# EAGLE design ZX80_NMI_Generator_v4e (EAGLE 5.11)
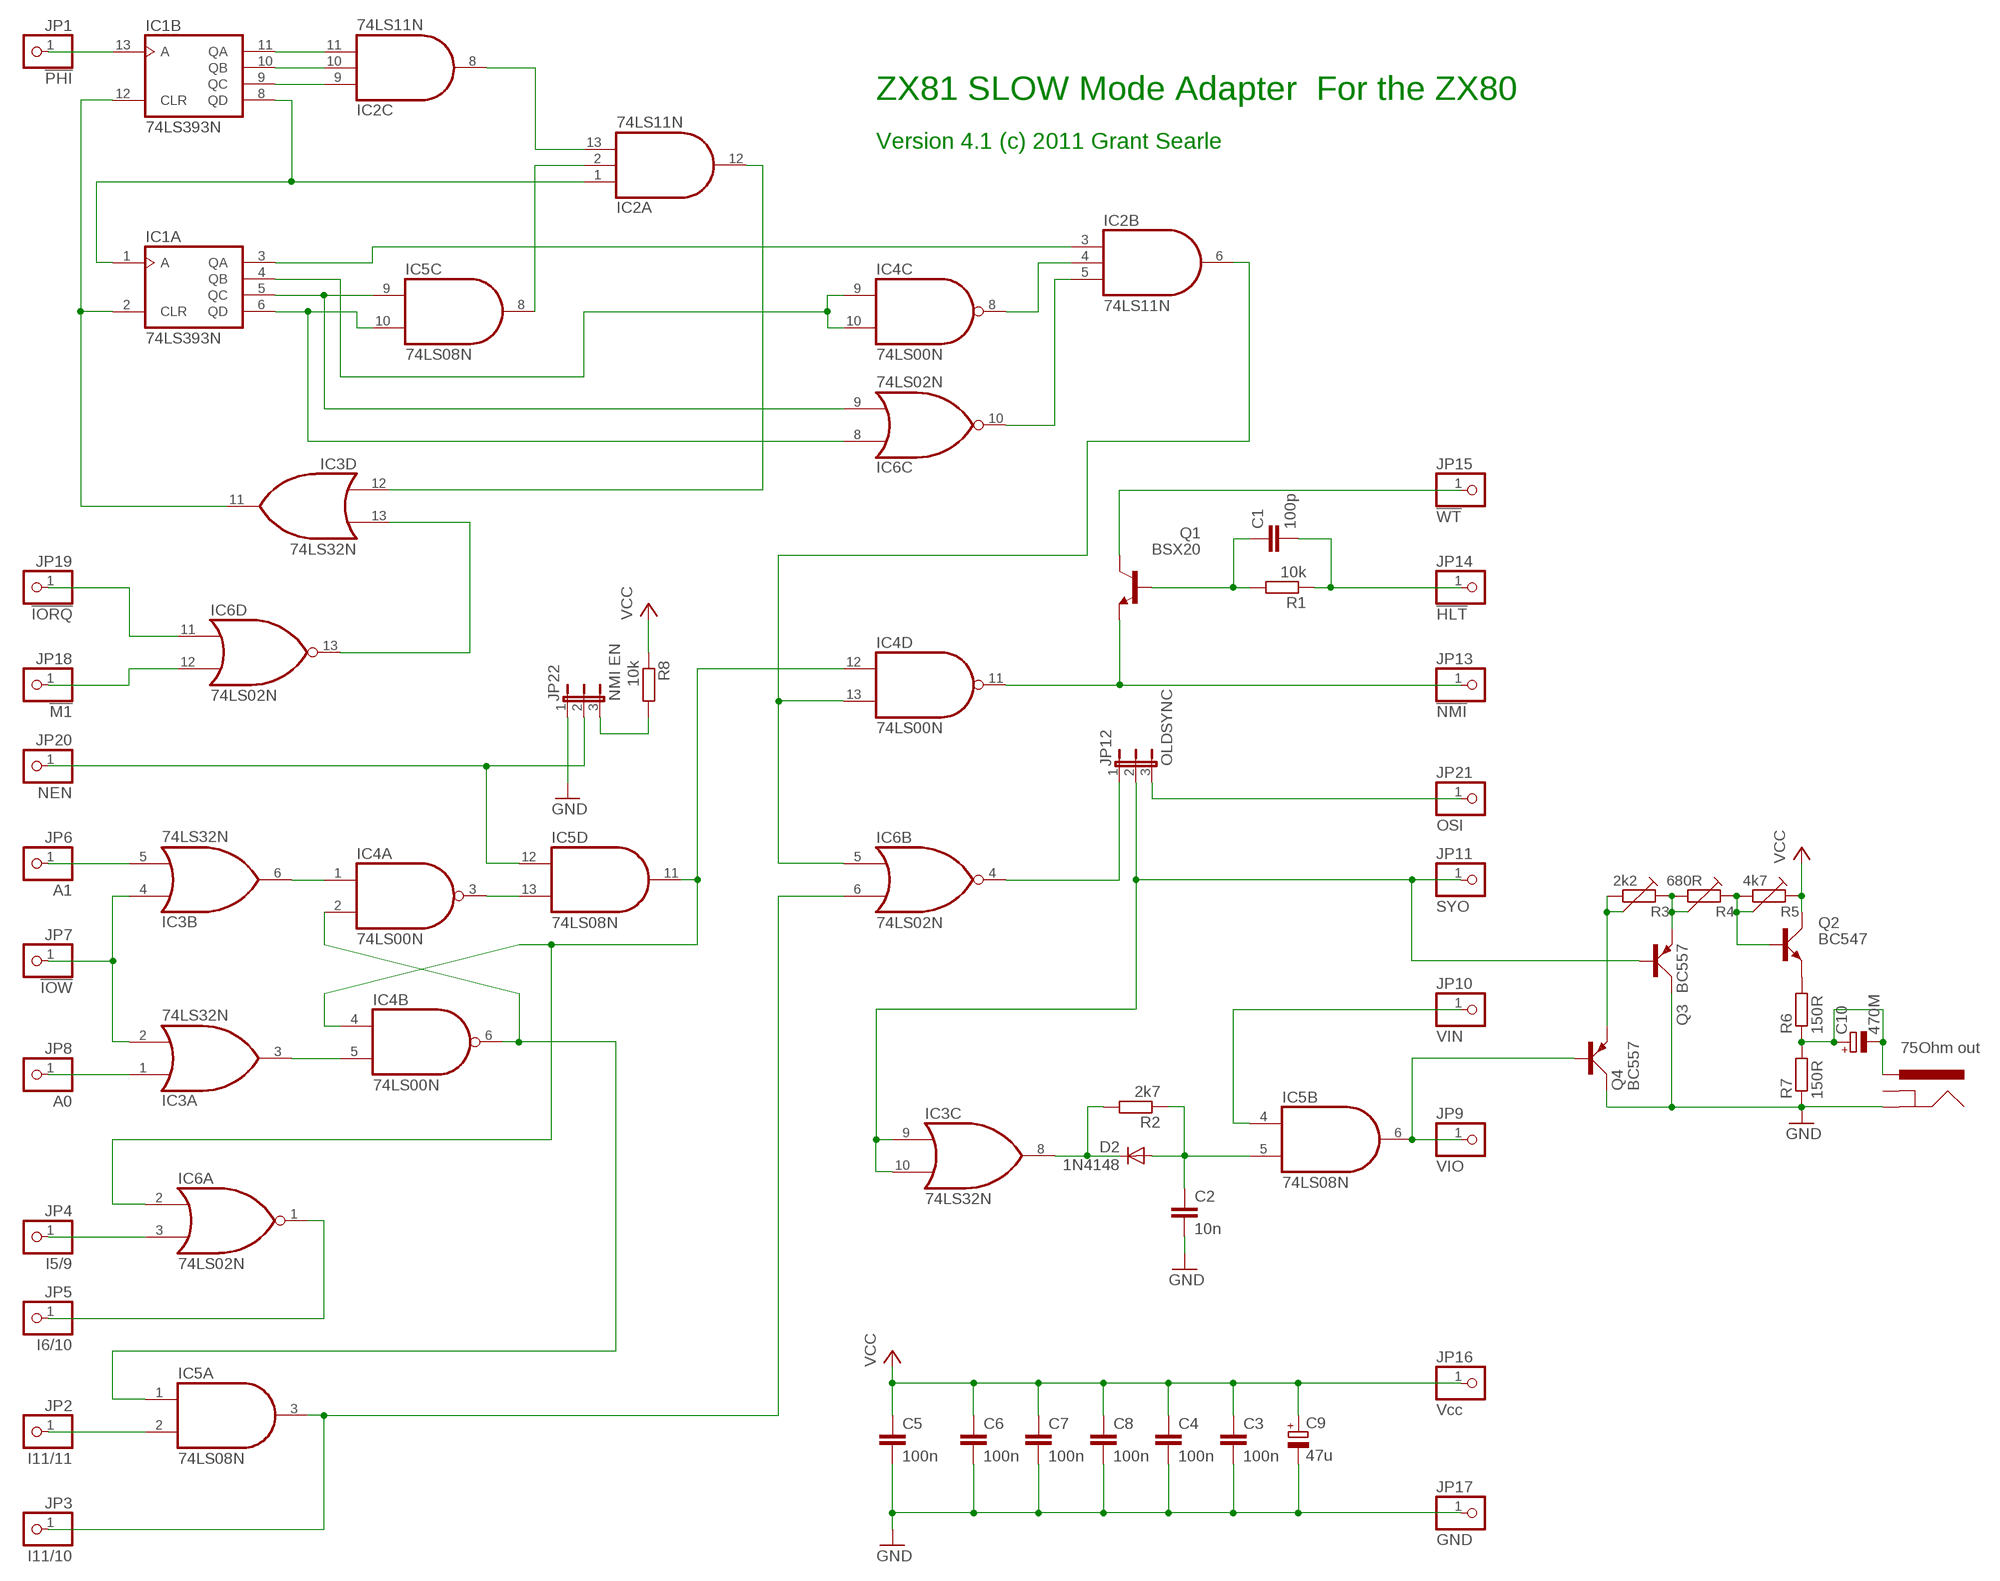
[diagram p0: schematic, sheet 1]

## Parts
C1  100p  C-EU025-025X050  [C025-025X050]
C2  10n  C-EU025-025X050  [C025-025X050]
C3  100n  C-EU025-025X050  [C025-025X050]
C4  100n  C-EU025-025X050  [C025-025X050]
C5  100n  C-EU025-025X050  [C025-025X050]
C6  100n  C-EU025-025X050  [C025-025X050]
C7  100n  C-EU025-025X050  [C025-025X050]
C8  100n  C-EU025-025X050  [C025-025X050]
C9  47u  CPOL-EUE2.5-7  [E2,5-7]
C10  470M  CPOL-EUE2.5-7  [E2,5-7]
D2  1N4148  1N4148DO35-10  [DO35-10]
IC1  74LS393N  [DIL14]
IC2  74LS11N  [DIL14]
IC3  74LS32N  [DIL14]
IC4  74LS00N  [DIL14]
IC5  74LS08N  [DIL14]
IC6  74LS02N  [DIL14]
J1  POWER_JACKRCA  [RCA]
JP1  !PHI  PINHD-1X1  [1X01]
JP2  I11/11  PINHD-1X1  [1X01]
JP3  I11/10  PINHD-1X1  [1X01]
JP4  I5/9  PINHD-1X1  [1X01]
JP5  I6/10  PINHD-1X1  [1X01]
JP6  A1  PINHD-1X1  [1X01]
JP7  !IOW  PINHD-1X1  [1X01]
JP8  A0  PINHD-1X1  [1X01]
JP9  VIO  PINHD-1X1  [1X01]
JP10  VIN  PINHD-1X1  [1X01]
JP11  SYO  PINHD-1X1  [1X01]
JP12  OLDSYNC  JP2E  [JP2]
JP13  !NMI  PINHD-1X1  [1X01]
JP14  !HLT  PINHD-1X1  [1X01]
JP15  !WT  PINHD-1X1  [1X01]
JP16  Vcc  PINHD-1X1  [1X01]
JP17  GND  PINHD-1X1  [1X01]
JP18  !M1  PINHD-1X1  [1X01]
JP19  !IORQ  PINHD-1X1  [1X01]
JP20  NEN  PINHD-1X1  [1X01]
JP21  OSI  PINHD-1X1  [1X01]
JP22  NMI EN  JP2E  [JP2]
Q1  BSX20  [TO18]
Q2  BC547  [SOT54A]
Q3  BC557  [SOT54A]
Q4  BC557  [SOT54A]
R1  10k  R-EU_0207/10  [0207/10]
R2  2k7  R-EU_0207/10  [0207/10]
R3  2k2  TRIMRPT6H  [PT6H]
R4  680R  TRIMRPT6H  [PT6H]
R5  4k7  TRIMRPT6H  [PT6H]
R6  150R  R-EU_0207/10  [0207/10]
R7  150R  R-EU_0207/10  [0207/10]
R8  10k  R-EU_0207/10  [0207/10]

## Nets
GND [power]: C2.2 C3.2 C4.2 C5.2 C6.2 C7.2 C8.2 C9.- J1.BARREL(GND) JP17.1 JP22.1 Q3.C Q4.C R7.1
N$1: IC3.1(A:I0) JP8.1
N$2: IC3.5(B:I1) JP6.1
N$3: IC1.13(B:A) JP1.1
N$4: IC1.2(A:CLR) IC1.12(B:CLR) IC3.11(D:O)
N$5: IC1.1(A:A) IC1.8(B:QD) IC2.1(A:I0)
N$6: IC2.8(C:O) IC2.13(A:I2)
N$7: IC4.2(A:I1) IC4.6(B:O) IC5.1(A:I0)
N$8: IC1.11(B:QA) IC2.11(C:I2)
N$9: IC1.10(B:QB) IC2.10(C:I1)
N$10: IC1.9(B:QC) IC2.9(C:I0)
N$11: IC1.5(A:QC) IC5.9(C:I0) IC6.9(C:I1)
N$12: IC5.2(A:I1) JP2.1
N$13: IC3.13(D:I1) IC6.13(D:O)
N$14: IC1.3(A:QA) IC2.3(B:I0)
N$15: IC5.3(A:O) IC6.6(B:I1) JP3.1
N$16: IC4.4(B:I0) IC4.12(D:I0) IC5.11(D:O) IC6.2(A:I0)
N$17: IC5.6(B:O) JP9.1 Q4.B
N$18: IC4.3(A:O) IC5.13(D:I1)
N$19: IC4.11(D:O) JP13.1 Q1.1(E)
N$20: JP15.1 Q1.3(C)
N$21: IC2.2(A:I1) IC5.8(C:O)
N$22: IC2.4(B:I1) IC4.8(C:O)
N$23: IC2.5(B:I2) IC6.10(C:O)
N$24: IC2.6(B:O) IC4.13(D:I1) IC6.5(B:I0)
N$25: IC3.2(A:I1) IC3.4(B:I0) JP7.1
N$26: IC3.3(A:O) IC4.5(B:I1)
N$27: IC3.6(B:O) IC4.1(A:I0)
N$28: IC2.12(A:O) IC3.12(D:I0)
N$29: IC5.4(B:I0) JP10.1
N$30: D2.C IC3.8(C:O) R2.2
N$31: IC1.6(A:QD) IC5.10(C:I1) IC6.8(C:I0)
N$32: IC6.12(D:I1) JP18.1
N$33: IC6.3(A:I1) JP4.1
N$34: C1.1 Q1.2(B) R1.2
N$35: C1.2 JP14.1 R1.1
N$36: IC6.11(D:I0) JP19.1
N$37: IC1.4(A:QB) IC4.9(C:I0) IC4.10(C:I1)
N$38: C2.1 D2.A IC5.5(B:I1) R2.1
N$39: IC6.4(B:O) JP12.1
N$40: IC5.12(D:I0) JP20.1 JP22.2
N$41: IC3.9(C:I0) IC3.10(C:I1) JP11.1 JP12.2 Q3.B
N$42: JP12.3 JP21.1
N$43: IC6.1(A:O) JP5.1
N$44: Q2.E R6.2
N$45: Q4.E R3.2 R3.3
N$46: Q3.E R3.1 R4.2 R4.3
N$47: Q2.B R4.1 R5.2 R5.3
N$49: C10.+ C10.- J1.BREAK(PWR) R6.1 R7.2
N$50: JP22.3 R8.2
VCC [power]: C3.1 C4.1 C5.1 C6.1 C7.1 C8.1 C9.+ JP16.1 Q2.C R5.1 R8.1
Unconnected: J1.SPRING(GNDBREAK)

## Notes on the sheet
- ZX81 SLOW Mode Adapter  For the ZX80
- Version 4.1 (c) 2011 Grant Searle
- 75Ohm out

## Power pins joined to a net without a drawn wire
GND: IC1.7(P:GND) IC2.7(P:GND) IC3.7(P:GND) IC4.7(P:GND) IC5.7(P:GND) IC6.7(P:GND)
VCC: IC1.14(P:VCC) IC2.14(P:VCC) IC3.14(P:VCC) IC4.14(P:VCC) IC5.14(P:VCC) IC6.14(P:VCC)

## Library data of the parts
C1-C8 = resistor:C-EU: CAPACITOR, European symbol
C9 C10 = rcl:CPOL-EU: POLARIZED CAPACITOR, European symbol
D2 = diode:1N4148: DIODE
IC1 = 74xx-us:74*393: Dual 4-bit decade and binary COUNTER
IC2 = 74xx-us:74*11: Triple 3-input AND gate
IC3 = 74xx-us:74*32: Quad 2-input OR gate
IC4 = 74xx-us:74*00: Quad 2-input NAND gate
IC5 = 74xx-us:74*08: Quad 2-input AND gate
IC6 = 74xx-us:74*02: Quad 2-input NOR gate
J1 = SparkFun:POWER_JACK: Power Jack This is the standard 5.5mm barrel jack for power. The PTH is the most common, proven, reliable, footprint. All others are experimental. The Slot footprint only works if the mill layer is transmitted to the PCB fab house so be warned. Spark Fun Electronics SKU : PRT-00119. Mating wall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
JP1-JP11 JP13-JP21 = pinhead:PINHD-1X1: PIN HEADER
JP12 JP22 = jumper:JP2E: JUMPER
Q1 = transistor-npn:BSX20*: NPN Transistor
Q2 = transistor-small-signal:BC547: NPN TRANSISTOR
Q3 Q4 = transistor-small-signal:BC557: PNP TRANSISTOR
R1 R2 R6-R8 = resistor:R-EU_: RESISTOR, European symbol
R3-R5 = #PaJa_30:TRIMR: Trimr

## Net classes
0 default: width 0.254 mm, clearance 0.254 mm
1 power: width 0.61 mm, clearance 0.254 mm

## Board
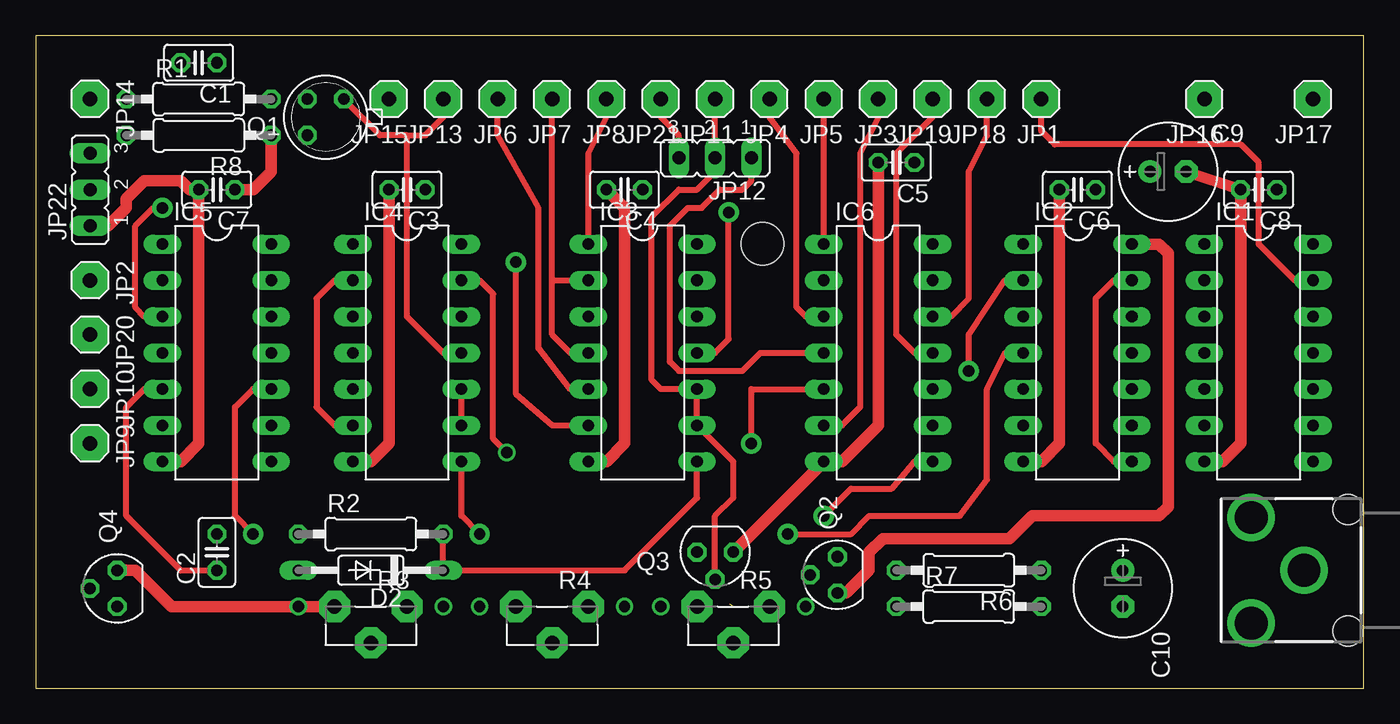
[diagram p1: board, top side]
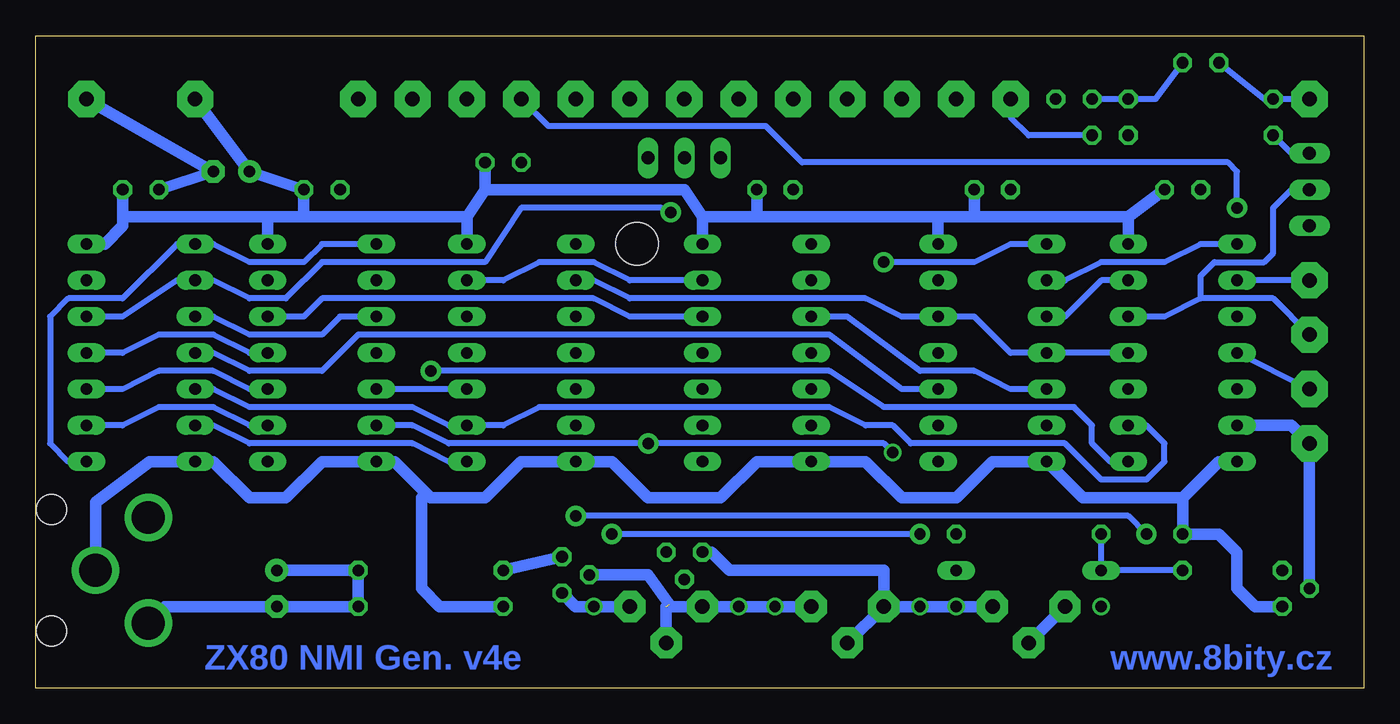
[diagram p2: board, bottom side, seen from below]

Size 93.09 x 45.72 mm. Coordinates in mm from the lower left corner, seen from the top.
Outline: 0,0 93.09,0 93.09,45.72 0,45.72 0,0
Copper layers (1*16): Top 0.035mm / dielectric 1.5mm / Bottom 0.035mm
Design rules "trida4_12.5mil": minimum track width 12.5mil, minimum drill 0.8mm, track to track 12.5mil, track to pad 12.5mil, pad to pad 12.5mil, via to via 12.5mil, smd to smd 8mil, copper to edge 0.1mm, drill to drill 1.25mm, minimum pad ring 10mil, minimum via ring 8mil, stop-mask expansion 4mil, vias tented up to drill 0mil, thermal gap 10mil
Holes 3 mm at 50.95,31.13

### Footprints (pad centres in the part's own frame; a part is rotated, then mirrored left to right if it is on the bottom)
C025-025X050 = drill 0.813 octagon: 1 -1.27,0; 2 1.27,0
E2,5-7 = drill 0.813 pad 1.6 round: + -1.27,0 | drill 0.813 pad 1.6 octagon: - 1.27,0
DO35-10 = drill 0.813 long: A 5.08,0; C -5.08,0
DIL14 = drill 0.813 long: 1 -7.62,-3.81; 2 -5.08,-3.81; 3 -2.54,-3.81; 4 0,-3.81; 5 2.54,-3.81; 6 5.08,-3.81; 7 7.62,-3.81; 8 7.62,3.81; 9 5.08,3.81; 10 2.54,3.81; 11 0,3.81; 12 -2.54,3.81; 13 -5.08,3.81; 14 -7.62,3.81
RCA = drill 2.3 round: BARREL 0,0; BREAK 3.7,3.7; SPRING 3.7,-3.7 | hole 2.1: -3.1,4.25; -3.1,-4.25
1X01 = drill 1.016 pad 2.54 octagon: 1 0,0
JP2 = drill 0.914 long: 1 -2.54,0; 2 0,0; 3 2.54,0
TO18 = drill 0.813 octagon: 1 -1.27,-1.27; 2 1.27,-1.27; 3 1.27,1.27
SOT54A = drill 0.813 octagon: B 0,1.905; C -1.27,0; E 1.27,0
0207/10 = drill 0.813 octagon: 1 -5.08,0; 2 5.08,0
PT6H = drill 1.016 pad 2.184 octagon: 1 -2.54,-1.27; 2 2.54,-1.27; 3 0,1.27

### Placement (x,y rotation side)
C1  11.43,43.81 180 top
C2  12.7,9.53 90 top
C3  26.04,34.92 180 top
C4  41.27,34.92 180 top
C5  60.33,36.83 180 top
C6  73.03,34.92 180 top
C7  12.7,34.92 180 top
C8  85.72,34.92 180 top
C9  79.38,36.2 0 top
C10  76.2,6.99 270 top
D2  23.5,8.26 180 top
IC1  85.72,23.5 270 top
IC2  73.03,23.5 270 top
IC3  42.55,23.5 270 top
IC4  26.04,23.5 270 top
IC5  12.7,23.5 270 top
IC6  59.05,23.5 270 top
J1  88.9,8.26 180 top
JP1  70.48,41.27 180 top
JP2  3.81,28.57 270 top
JP3  59.05,41.27 180 top
JP4  51.44,41.27 180 top
JP5  55.24,41.27 180 top
JP6  32.38,41.27 180 top
JP7  36.2,41.27 180 top
JP8  40.01,41.27 180 top
JP9  3.81,17.14 270 top
JP10  3.81,20.95 270 top
JP11  47.62,41.27 180 top
JP12  47.62,37.15 180 top
JP13  28.57,41.27 180 top
JP14  3.81,41.27 270 top
JP15  24.77,41.27 180 top
JP16  81.92,41.27 180 top
JP17  89.53,41.27 180 top
JP18  66.67,41.27 180 top
JP19  62.87,41.27 180 top
JP20  3.81,24.77 270 top
JP21  43.81,41.27 180 top
JP22  3.81,34.92 90 top
Q1  20.32,40.01 180 top
Q2  56.2,7.94 90 top
Q3  47.62,9.53 180 top
Q4  5.71,6.99 90 top
R1  11.43,41.27 0 top
R2  23.5,10.79 0 top
R3  23.5,4.45 180 top
R4  36.2,4.45 180 top
R5  48.9,4.45 180 top
R6  65.41,8.26 180 top
R7  65.41,5.71 0 top
R8  11.43,38.73 180 top

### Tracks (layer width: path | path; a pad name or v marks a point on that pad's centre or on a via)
GND
  Top 0.813: IC1.7 83.19,15.88 84.45,17.14 C8.2 C9.- | C6.2 71.75,17.14 70.48,15.88 IC2.7 | C5.2 59.05,18.41 56.52,15.88 IC6.7 Q3.C | C4.2 41.27,33.66 41.27,17.14 40.01,15.88 IC3.7 | C3.2 24.77,17.14 23.5,15.88 IC4.7 | IC5.7 10.16,15.88 11.43,17.14 C7.2 10.79,34.92 10.16,35.56 7.62,35.56 6.35,34.29 6.35,33.66 5.08,32.38 JP22.1
  Bottom 0.61: IC1.7 82.55,15.88
  Bottom 0.813: IC5.7 10.16,15.88 12.7,13.34 | 12.7,13.34 19.68,13.34 IC4.7 26.04,15.88 28.57,13.34 32.38,13.34 34.92,15.88 IC3.7 42.55,15.88 45.09,13.34 50.16,13.34 52.7,15.88 IC6.7 59.05,15.88 61.59,13.34 65.41,13.34 65.72,13.65 | JP17.1 C9.- C8.2 | 65.72,13.65 67.94,15.88 IC2.7 73.03,15.88 75.56,13.34 78.11,13.34 80.64,15.88 IC1.7 | 12.7,13.34 C2.2 10.16,10.79 8.89,9.53 8.89,6.99 7.62,5.71 Q4.C | J1.BARREL 88.9,13.02 85.09,15.88 82.55,15.88 | R7.1 64.77,5.71 66.04,6.99 66.04,13.34 65.72,13.65
N$1
  Top 0.406: JP8.1 40.01,40.01 38.73,37.47 IC3.1
N$2
  Top 0.406: IC3.5 37.47,20.95 35.24,23.81 35.24,33.66 32.38,38.73 JP6.1
N$3
  Top 0.406: IC1.13 88.27,28.57 85.72,31.11 85.72,36.83 84.45,38.1 71.44,38.1 70.48,39.05 JP1.1
N$4  (via drill 0.8 pad 1.42)
  Top 0.406: v48.58,33.34 48.58,24.45 47.62,23.5 IC3.11
  Bottom 0.406: IC1.12 87,26.04 83.19,28.57 IC1.2 80.64,28.57 78.11,27.3 75.56,27.3 73.03,29.84 61.59,29.84 59.05,33.66 49.21,33.66 v48.58,33.34
N$5
  Bottom 0.406: IC1.8 90.81,15.88 92.08,17.14 92.08,26.04 90.81,27.3 87,27.3 83.19,31.11 IC1.1 80.64,31.11 78.11,29.84 74.3,29.84 73.03,31.11 IC2.1
N$6
  Top 0.406: IC2.13 75.56,28.57 74.3,27.3 74.3,17.14 75.56,15.88 IC2.8
N$7
  Top 0.406: IC4.6 20.95,18.41 19.68,19.68 19.68,27.3 20.95,28.57 IC4.2
  Bottom 0.406: IC5.1 11.43,31.11 13.97,29.84 18.41,29.84 20.95,28.57 IC4.2
N$8
  Bottom 0.406: IC1.11 87,23.5 84.45,24.77 80.64,24.77 78.11,23.5 IC2.11
N$9
  Bottom 0.406: IC1.10 87,20.95 84.45,22.23 80.64,22.23 78.11,20.95 IC2.10
N$10
  Bottom 0.406: IC1.9 87,18.41 84.45,19.68 80.64,19.68 78.11,18.41 IC2.9
N$11
  Bottom 0.406: IC5.9 15.24,18.41 13.97,17.14 13.97,15.88 15.24,14.61 18.41,14.61 20.95,17.14 31.75,17.14 33.02,18.41 34.92,18.41 37.47,19.68 57.78,19.68 60.33,18.41 IC6.9 64.14,18.41 66.67,19.68 78.11,19.68 80.64,20.95 IC1.5
N$12
  Bottom 0.406: JP2.1 IC5.2
N$13
  Bottom 0.406: IC3.13 51.44,28.57 53.98,29.84 57.78,29.84 60.33,28.57 IC6.13
N$14
  Bottom 0.406: IC1.3 80.64,26.04 78.11,24.77 73.03,24.77 71.75,26.04 IC2.3
N$15  (via drill 0.8 pad 1.42)
  Top 0.406: IC6.6 56.52,18.41 57.78,19.68 57.78,37.47 59.05,40.01 JP3.1 | IC5.3 7.62,26.04 6.99,26.67 6.99,32.38 8.26,33.66 v8.89,33.66
  Bottom 0.406: v8.89,33.66 8.89,36.2 9.53,36.83 39.37,36.83 41.91,39.37 57.15,39.37 JP3.1
N$16
  Bottom 0.406: IC5.11 IC4.4 24.77,23.5 27.3,26.04 IC4.12 32.38,26.04 34.92,27.3 51.44,27.3 53.98,28.57 IC6.2
N$17
  Bottom 0.813: IC5.6 5.08,18.41 JP9.1 Q4.B
N$18
  Bottom 0.406: IC4.3 20.95,26.04 18.41,28.57 IC5.13
N$19
  Top 0.406: IC4.11 28.57,23.5 26.04,26.04 26.04,38.73 | Q1.1 24.13,38.73 26.04,38.73 | 26.04,38.73 27.3,38.73 28.57,40.01 JP13.1
N$20
  Bottom 0.406: Q1.3 23.5,38.73 24.77,40.01 JP15.1
N$21  (via drill 0.8 pad 1.42)
  Top 0.406: IC2.2 67.94,28.57 65.41,24.77 v65.41,22.23
  Bottom 0.406: IC5.8 17.78,15.88 19.05,17.14 19.05,18.41 20.32,19.68 33.66,19.68 37.47,22.23 v65.41,22.23
N$22  (via drill 0.8 pad 1.42)
  Top 0.406: IC4.8 29.84,12.06 v31.11,10.79 | v52.7,10.79 57.15,10.79 58.42,12.06 64.77,12.06 66.67,14.61 66.67,20.95 67.94,23.5 IC2.4
  Bottom 0.406: v31.11,10.79 v52.7,10.79
N$23
  Bottom 0.406: IC6.10 IC2.5
N$24  (via drill 0.8, 0.8 pad 1.42)
  Top 0.406: v50.16,17.14 50.16,20.95 IC6.5 | IC4.13 31.11,28.57 32.07,27.62 32.07,17.46 v33.02,16.51
  Bottom 0.406: IC2.6 66.67,18.41 64.14,17.14 v50.16,17.14 33.66,17.14 v33.02,16.51
N$25
  Top 0.406: IC3.4 37.47,23.5 36.2,24.77 36.2,28.57 | 36.2,28.57 IC3.2 | 36.2,28.57 JP7.1
N$26
  Bottom 0.406: IC3.3 36.2,26.04 31.11,22.23 27.3,22.23 24.77,20.95 IC4.5
N$27  (via drill 0.8 pad 1.42)
  Top 0.406: IC3.6 36.2,18.41 33.66,20.64 v33.66,29.84
  Bottom 0.406: IC4.1 24.77,31.11 27.3,29.84 v33.66,29.84
N$28
  Bottom 0.406: IC2.12 74.3,26.04 73.03,27.3 53.98,27.3 51.44,26.04 IC3.12
N$29
  Bottom 0.406: JP10.1 IC5.4
N$30
  Top 0.406: IC3.8 46.35,13.34 41.27,8.26 D2.C R2.2
N$31  (via drill 0.8 pad 1.42)
  Top 0.406: IC5.10 15.24,20.95 13.97,19.68 13.97,12.06 v15.24,10.79 | IC6.8 61.59,15.88 60.01,13.97 57.15,13.97 v55.24,12.06
  Bottom 0.406: v15.24,10.79 16.51,12.06 v55.24,12.06 | IC1.6 80.64,18.41 78.11,17.14 66.67,17.14 64.14,15.88 IC6.8
N$32
  Top 0.406: IC6.12 64.14,26.04 65.41,27.3 65.41,36.2 66.67,38.73 JP18.1
N$33
  Top 0.406: IC6.3 53.98,26.04 53.34,26.67 53.34,37.47 51.44,40.01 JP4.1
N$34
  Bottom 0.406: Q1.2 R1.2 14.61,41.27 C1.1
N$35
  Bottom 0.406: C1.2 6.99,41.27 R1.1 JP14.1
N$36
  Top 0.406: IC6.11 61.59,23.5 60.33,24.77 60.33,37.47 62.87,40.01 JP19.1
N$37
  Top 0.406: IC4.9 IC4.10
  Bottom 0.406: IC4.10 32.38,20.95 37.47,24.77 70.48,24.77 73.03,22.23 78.11,22.23 80.64,23.5 IC1.4
N$38
  Top 0.406: IC5.5 7.62,20.95 6.35,19.68 6.35,12.06 10.16,8.26 C2.1
  Bottom 0.406: C2.1 D2.A R2.1
N$39
  Top 0.406: IC6.4 50.8,23.5 49.53,22.23 45.09,22.23 44.45,22.86 44.45,32.38 45.72,33.66 46.67,33.66 47.94,34.92 49.53,34.92 50.16,35.56 JP12.1
N$40
  Bottom 0.406: IC5.12 13.97,26.04 11.43,27.3 | JP20.1 6.35,27.3 11.43,27.3 | JP22.2 5.08,34.92 6.35,33.66 6.35,30.48 6.99,29.84 10.48,29.84 11.43,28.89 11.43,27.3
N$41
  Top 0.406: JP11.1 JP12.2 47.62,36.2 46.35,34.92 45.09,34.92 43.18,33.02 43.18,21.59 43.81,20.95 IC3.10 IC3.9 48.9,15.88 48.9,13.34 47.62,12.06 Q3.B
N$42
  Top 0.406: JP12.3 45.09,38.73 43.81,40.01 JP21.1
N$43
  Top 0.406: IC6.1 JP5.1
N$44
  Bottom 0.813: Q2.E R6.2
N$45  (via drill 0.8)
  Top 0.813: Q4.E 6.99,8.26 9.53,5.71 v18.41,5.71 R3.2
  Bottom 0.813: R3.3 R3.2
N$46  (via drill 0.8)
  Bottom 0.813: R3.1 v28.57,5.71 v31.11,5.71 R4.2 | R4.2 33.66,8.26 44.45,8.26 45.72,9.53 Q3.E | R4.3 R4.2
N$47  (via drill 0.8)  (1 unrouted)
  Bottom 0.813: R4.1 v41.27,5.71 v43.81,5.71 R5.2 48.58,5.71 50.16,7.94 Q2.B | R5.3 48.9,5.71
N$49
  Bottom 0.813: C10.+ R6.1 R7.2 C10.- 84.04,5.71 J1.BREAK
N$50
  Bottom 0.406: JP22.3 5.08,37.47 R8.2
VCC  (via drill 0.8)
  Top 0.813: Q2.C 56.83,6.67 58.42,8.26 58.42,9.53 59.37,10.48 68.26,10.48 69.85,12.06 78.74,12.06 79.38,12.7 79.38,30.48 78.74,31.11 IC2.14 | C7.1 15.24,34.92 16.51,36.2 R8.1
  Bottom 0.813: 27.3,33.02 29.84,33.02 | 29.84,33.02 42.55,33.02 | 42.55,33.02 46.35,33.02 | 46.35,33.02 47.62,34.92 61.59,34.92 | 61.59,34.92 62.87,33.02 | 62.87,33.02 74.3,33.02 | 74.3,33.02 76.83,33.02 | 76.83,33.02 87,33.02 | 87,33.02 87,32.38 88.27,31.11 IC1.14 | 87,33.02 C8.1 | 76.83,33.02 IC2.14 | 74.3,33.02 C6.1 C9.+ JP16.1 | 62.87,33.02 IC6.14 | 61.59,34.92 C5.1 | 46.35,33.02 IC3.14 | 42.55,33.02 C4.1 | 29.84,33.02 IC4.14 | 27.3,33.02 C3.1 | 16.51,33.02 27.3,33.02 | C7.1 16.51,33.02 | 16.51,33.02 IC5.14 | R5.1 v53.98,5.71 55.24,5.71 Q2.C

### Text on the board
Bottom: www.8bity.cz | ZX80 NMI Gen. v4e
tValues: ZX80 NMI Generator v4.1 by G. Searle (PCB rev. E by Martin + EC1045) | www.8bity.cz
